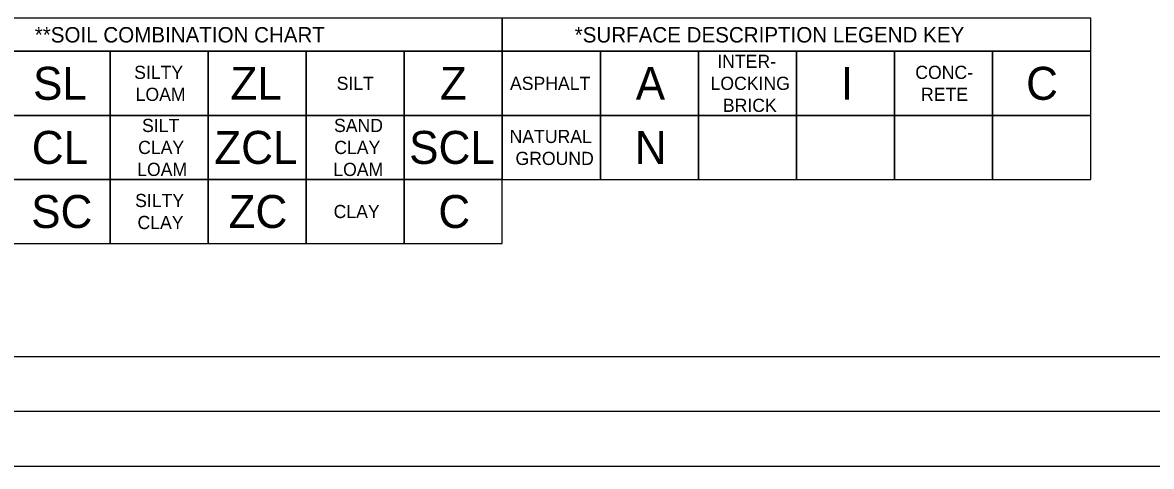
# Model space of a CAD drawing. Extents: x 14330 to 16126, y 15844 to 16994.
# Drawn here: x 14784 to 15298, y 15844 to 16046 of the extents above; entities that cross this region are included whole.
import ezdxf

# ---------------------------------------------------------------- set-up
doc = ezdxf.new("R2010")
doc.units = 0
for name, color, linetype in [('RD_SHT_Bndy', 7, 'Continuous'), ('RD_SHT_Iplotshp', 7, 'Continuous'), ('RD_SHT_TX', 7, 'Continuous')]:
    doc.layers.add(name, color=color, linetype=linetype)

msp = doc.modelspace()

# ---------------------------------------------------------------- linework, layer by layer
at = {"layer": 'RD_SHT_Bndy'}
for p, q in [((14430.85, 15893.63), (16105.85, 15893.63)), ((16108.25, 15868.63), (14348.25, 15868.63)), ((16108.25, 15843.63), (14348.25, 15843.63))]:
    msp.add_line(p, q, dxfattribs=at)
for points in [[(14734.84, 16032.5), (15002.74, 16032.5), (15002.74, 16047.5), (14734.84, 16047.5)], [(15002.74, 16032.5), (15270.63, 16032.5), (15270.63, 16047.5), (15002.74, 16047.5)], [(14779.49, 16003.34), (14824.14, 16003.34), (14824.14, 16032.5), (14779.49, 16032.5)], [(14824.14, 16003.34), (14868.79, 16003.34), (14868.79, 16032.5), (14824.14, 16032.5)], [(14913.44, 16003.34), (14958.09, 16003.34), (14958.09, 16032.5), (14913.44, 16032.5)], [(14958.09, 16003.34), (15002.74, 16003.34), (15002.74, 16032.5), (14958.09, 16032.5)], [(15002.74, 16003.34), (15047.39, 16003.34), (15047.39, 16032.5), (15002.74, 16032.5)], [(15047.39, 16003.34), (15092.04, 16003.34), (15092.04, 16032.5), (15047.39, 16032.5)], [(15092.04, 16003.34), (15136.69, 16003.34), (15136.69, 16032.5), (15092.04, 16032.5)], [(15136.69, 16003.34), (15181.34, 16003.34), (15181.34, 16032.5), (15136.69, 16032.5)], [(15181.34, 16003.34), (15225.98, 16003.34), (15225.98, 16032.5), (15181.34, 16032.5)], [(15225.98, 16003.34), (15270.63, 16003.34), (15270.63, 16032.5), (15225.98, 16032.5)], [(14779.49, 15974.18), (14824.14, 15974.18), (14824.14, 16003.34), (14779.49, 16003.34)], [(14824.14, 15974.18), (14868.79, 15974.18), (14868.79, 16003.34), (14824.14, 16003.34)], [(14868.79, 15974.18), (14913.44, 15974.18), (14913.44, 16003.34), (14868.79, 16003.34)], [(14913.44, 15974.18), (14958.09, 15974.18), (14958.09, 16003.34), (14913.44, 16003.34)], [(14958.09, 15974.18), (15002.74, 15974.18), (15002.74, 16003.34), (14958.09, 16003.34)], [(15002.74, 15974.18), (15047.39, 15974.18), (15047.39, 16003.34), (15002.74, 16003.34)], [(15047.39, 15974.18), (15092.04, 15974.18), (15092.04, 16003.34), (15047.39, 16003.34)], [(15092.04, 15974.18), (15136.69, 15974.18), (15136.69, 16003.34), (15092.04, 16003.34)], [(15136.69, 15974.18), (15181.34, 15974.18), (15181.34, 16003.34), (15136.69, 16003.34)], [(15181.34, 15974.18), (15225.98, 15974.18), (15225.98, 16003.34), (15181.34, 16003.34)], [(15225.98, 15974.18), (15270.63, 15974.18), (15270.63, 16003.34), (15225.98, 16003.34)], [(14779.49, 15945.03), (14824.14, 15945.03), (14824.14, 15974.18), (14779.49, 15974.18)], [(14824.14, 15945.03), (14868.79, 15945.03), (14868.79, 15974.18), (14824.14, 15974.18)], [(14868.79, 15945.03), (14913.44, 15945.03), (14913.44, 15974.18), (14868.79, 15974.18)], [(14913.44, 15945.03), (14958.09, 15945.03), (14958.09, 15974.18), (14913.44, 15974.18)], [(14958.09, 15945.03), (15002.74, 15945.03), (15002.74, 15974.18), (14958.09, 15974.18)]]:
    msp.add_lwpolyline(points, close=True, dxfattribs=at)
at = {"layer": 'RD_SHT_Iplotshp'}
msp.add_lwpolyline([(14329.65, 16968.63), (16125.65, 16968.63), (16125.65, 15868.63), (14329.65, 15868.63)], close=True, dxfattribs=at)
at = {"layer": 'RD_SHT_TX'}
msp.add_lwpolyline([(14868.79, 16003.34), (14913.44, 16003.34), (14913.44, 16032.5), (14868.79, 16032.5)], close=True, dxfattribs=at)

# ---------------------------------------------------------------- texts
for s, p in [('**SOIL COMBINATION CHART', (14789.87, 16036.5)), ('*SURFACE DESCRIPTION LEGEND KEY', (15035.69, 16036.5))]:
    msp.add_text(s, height=7, rotation=360, dxfattribs=at).set_placement(p)
for s, height, p in [('INTER-', 6, (15100.61, 16024.92)), ('SL', 15, (14789.08, 16010.42)), ('SILTY', 6, (14835.12, 16019.92)), ('ZL', 15, (14878.95, 16010.42)), ('Z', 15, (14974.33, 16010.42)), ('A', 15, (15063.48, 16010.42)), ('I', 15, (15156.89, 16010.42)), ('CONC-', 6, (15190.76, 16019.92)), ('C', 15, (15241.23, 16010.42)), ('SILT', 6, (14927.31, 16014.92)), ('ASPHALT', 6, (15006.23, 16014.92)), ('LOCKING', 6, (15097.54, 16014.92)), ('LOAM', 6, (14835.79, 16009.92)), ('RETE', 6, (15193.38, 16009.92)), ('BRICK', 6, (15103.16, 16004.92)), ('SILT', 6, (14838.71, 15995.76)), ('SAND', 6, (14926.12, 15995.76)), ('CL', 15, (14788.51, 15981.26)), ('ZCL', 15, (14871.59, 15981.26)), ('SCL', 15, (14960.32, 15981.26)), ('NATURAL', 6, (15006.04, 15990.76)), ('N', 15, (15063.06, 15981.26)), ('CLAY', 6, (14836.92, 15985.76)), ('CLAY', 6, (14926.22, 15985.76)), ('GROUND', 6, (15008.73, 15980.76)), ('LOAM', 6, (14836.49, 15975.76)), ('LOAM', 6, (14925.79, 15975.76)), ('SC', 15, (14788.23, 15952.11)), ('SILTY', 6, (14835.55, 15961.61)), ('ZC', 15, (14878.1, 15952.11)), ('C', 15, (14973.62, 15952.11)), ('CLAY', 6, (14925.93, 15956.61)), ('CLAY', 6, (14836.64, 15951.61))]:
    msp.add_text(s, height=height, dxfattribs=at).set_placement(p)

doc.saveas('drawing.dxf')
